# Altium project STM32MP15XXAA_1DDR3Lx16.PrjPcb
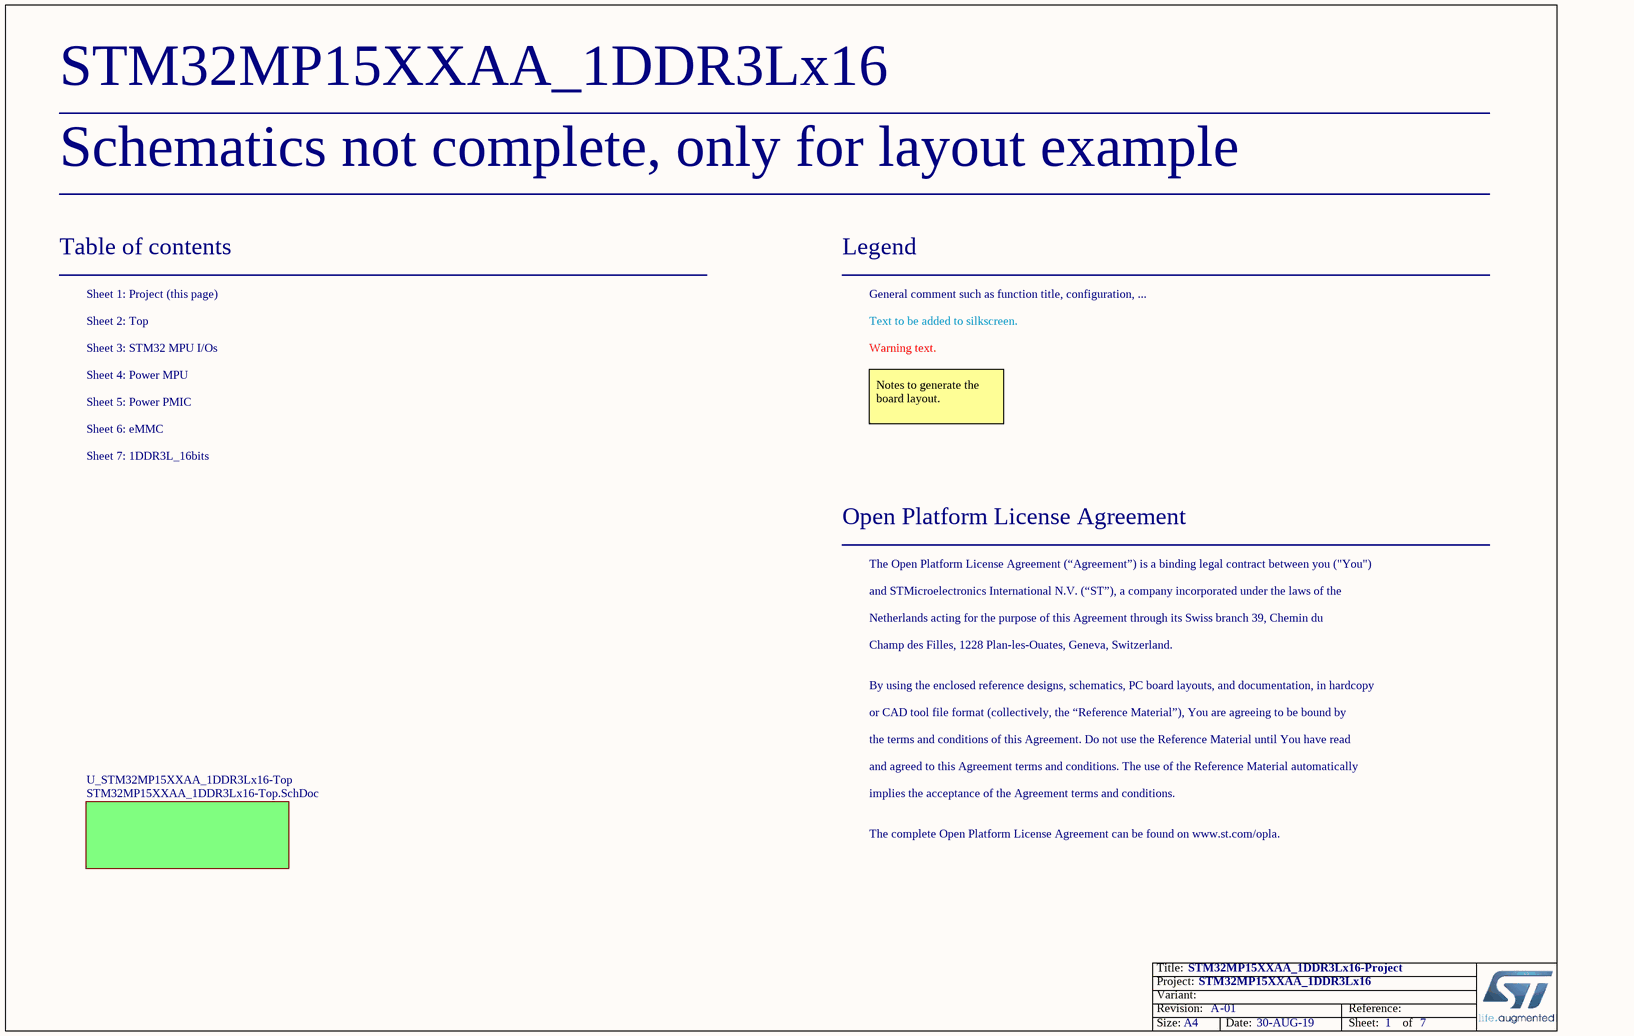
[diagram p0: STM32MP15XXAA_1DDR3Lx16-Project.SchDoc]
Board_Assembly_Revision: 01; Board_Document_Date: 30-AUG-19; Board_Name: STM32MP15XXAA_1DDR3Lx16; Board_PCB_Revision: A
7 sheets, 100 parts. Net scope: flat (ports and power ports of the same name join across sheets).
Board file: STM32MP15XXAA_1DDR3Lx16_A01.PcbDoc
Sheets:
  STM32MP15XXAA_1DDR3Lx16-Project.SchDoc
    U_STM32MP15XXAA_1DDR3Lx16-Top = STM32MP15XXAA_1DDR3Lx16-Top.SchDoc
      U_Power_PMIC = Power_PMIC.SchDoc
      U_Power_MPU = Power_MPU.SchDoc
      U_eMMC = eMMC.SchDoc
      U_STM32_MPU_IOs = STM32_MPU_IOs.SchDoc
      U_1DDR3L_16bits = 1DDR3L_16bits.SchDoc

## Sheet STM32MP15XXAA_1DDR3Lx16-Project.SchDoc: STM32MP15XXAA_1DDR3Lx16-Project
size A4; ApprovedBy: Not used; CheckedBy: Not used; Author: Not used; CompanyName: STMicroelectronics; DrawnBy: Not used; Engineer: Not used; Organization: Not used; Address1: Not used; Address2: Not used; Address3: Not used; Address4: Not used; DocumentNumber: Not used; Revision: Not used; SheetNumber: 1; SheetTotal: 7

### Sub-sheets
U_STM32MP15XXAA_1DDR3Lx16-Top = STM32MP15XXAA_1DDR3Lx16-Top.SchDoc: no entries

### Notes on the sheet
- Schematics not complete, only for layout example
- Table of contents
- Sheet 1: Project (this page)
- Legend
- General comment such as function title, configuration, ...
- Sheet 2: Top
- Sheet 3: STM32 MPU I/Os
- Sheet 4: Power MPU
- Text to be added to silkscreen.
- Warning text.
- Sheet 5: Power PMIC
- Sheet 6: eMMC
- Notes to generate the board layout.
- Sheet 7: 1DDR3L_16bits
- Open Platform License Agreement
- The Open Platform License Agreement (“Agreement”) is a binding legal contract between you ("You")
- and STMicroelectronics International N.V. (“ST”), a company incorporated under the laws of the
- Netherlands acting for the purpose of this Agreement through its Swiss branch 39, Chemin du
- Champ des Filles, 1228 Plan-les-Ouates, Geneva, Switzerland.
- By using the enclosed reference designs, schematics, PC board layouts, and documentation, in hardcopy
- or CAD tool file format (collectively, the “Reference Material”), You are agreeing to be bound by
- the terms and conditions of this Agreement. Do not use the Reference Material until You have read
- and agreed to this Agreement terms and conditions. The use of the Reference Material automatically
- implies the acceptance of the Agreement terms and conditions.
- The complete Open Platform License Agreement can be found on www.st.com/opla.

## Sheet STM32MP15XXAA_1DDR3Lx16-Top.SchDoc: STM32MP15XXAA_1DDR3Lx16-TOP
size A4; Date: Not used; ApprovedBy: Not used; CheckedBy: Not used; Author: Not used; CompanyName: STMicroelectronics; DrawnBy: Not used; Engineer: Not used; Organization: Not used; Address1: Not used; Address2: Not used; Address3: Not used; Address4: Not used; DocumentNumber: Not used; Revision: Not used; SheetNumber: 2; SheetTotal: 7
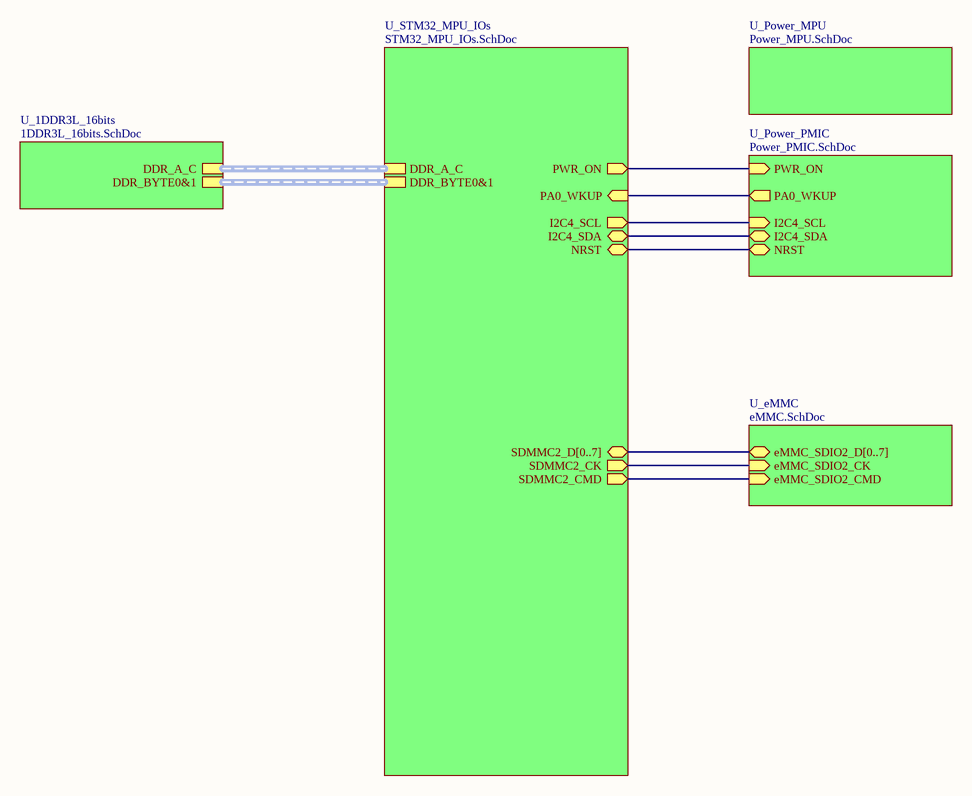
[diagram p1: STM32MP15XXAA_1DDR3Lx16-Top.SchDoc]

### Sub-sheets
U_1DDR3L_16bits = 1DDR3L_16bits.SchDoc: DDR_BYTE0&1 (harness DDR_BYTE_0&1), DDR_A_C (harness DDR_A_C)
U_eMMC = eMMC.SchDoc: eMMC_SDIO2_CK (in), eMMC_SDIO2_D[0..7] (bidir), eMMC_SDIO2_CMD (in)
U_Power_MPU = Power_MPU.SchDoc: no entries
U_Power_PMIC = Power_PMIC.SchDoc: I2C4_SDA (bidir), I2C4_SCL (in), PA0_WKUP (out), NRST (bidir), PWR_ON (in)
U_STM32_MPU_IOs = STM32_MPU_IOs.SchDoc: PA0_WKUP (in), NRST (bidir), PWR_ON (out), I2C4_SCL (out), I2C4_SDA (bidir), DDR_BYTE0&1 (harness DDR_BYTE_0&1), DDR_A_C (harness DDR_A_C), SDMMC2_D[0..7] (bidir), SDMMC2_CMD (out), SDMMC2_CK (out)

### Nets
(unnamed): sheet U_Power_PMIC/I2C4_SDA, sheet U_STM32_MPU_IOs/I2C4_SDA
(unnamed): sheet U_Power_PMIC/I2C4_SCL, sheet U_STM32_MPU_IOs/I2C4_SCL  [a separate net that carries the same name]
(unnamed): sheet U_Power_PMIC/PA0_WKUP, sheet U_STM32_MPU_IOs/PA0_WKUP  [a separate net that carries the same name]
(unnamed): sheet U_Power_PMIC/NRST, sheet U_STM32_MPU_IOs/NRST  [a separate net that carries the same name]
(unnamed): sheet U_Power_PMIC/PWR_ON, sheet U_STM32_MPU_IOs/PWR_ON  [a separate net that carries the same name]
(unnamed): sheet U_eMMC/eMMC_SDIO2_CK, sheet U_STM32_MPU_IOs/SDMMC2_CK  [a separate net that carries the same name]
(unnamed): sheet U_eMMC/eMMC_SDIO2_CMD, sheet U_STM32_MPU_IOs/SDMMC2_CMD  [a separate net that carries the same name]

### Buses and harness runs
bus sheet U_eMMC/eMMC_SDIO2_D[0..7] = sheet U_STM32_MPU_IOs/SDMMC2_D[0..7]
harness sheet U_1DDR3L_16bits/DDR_A_C = sheet U_STM32_MPU_IOs/DDR_A_C
harness sheet U_1DDR3L_16bits/DDR_BYTE0&1 = sheet U_STM32_MPU_IOs/DDR_BYTE0&1

## Sheet Power_PMIC.SchDoc: Power_PMIC
size A3; CompanyName: STMicroelectronics; Organization: Microcontrollers Division; Address1: 12, Rue Jules HOROWITZ; Address2: 38019 Grenoble; Address3: FRANCE; SheetNumber: 5; SheetTotal: 7
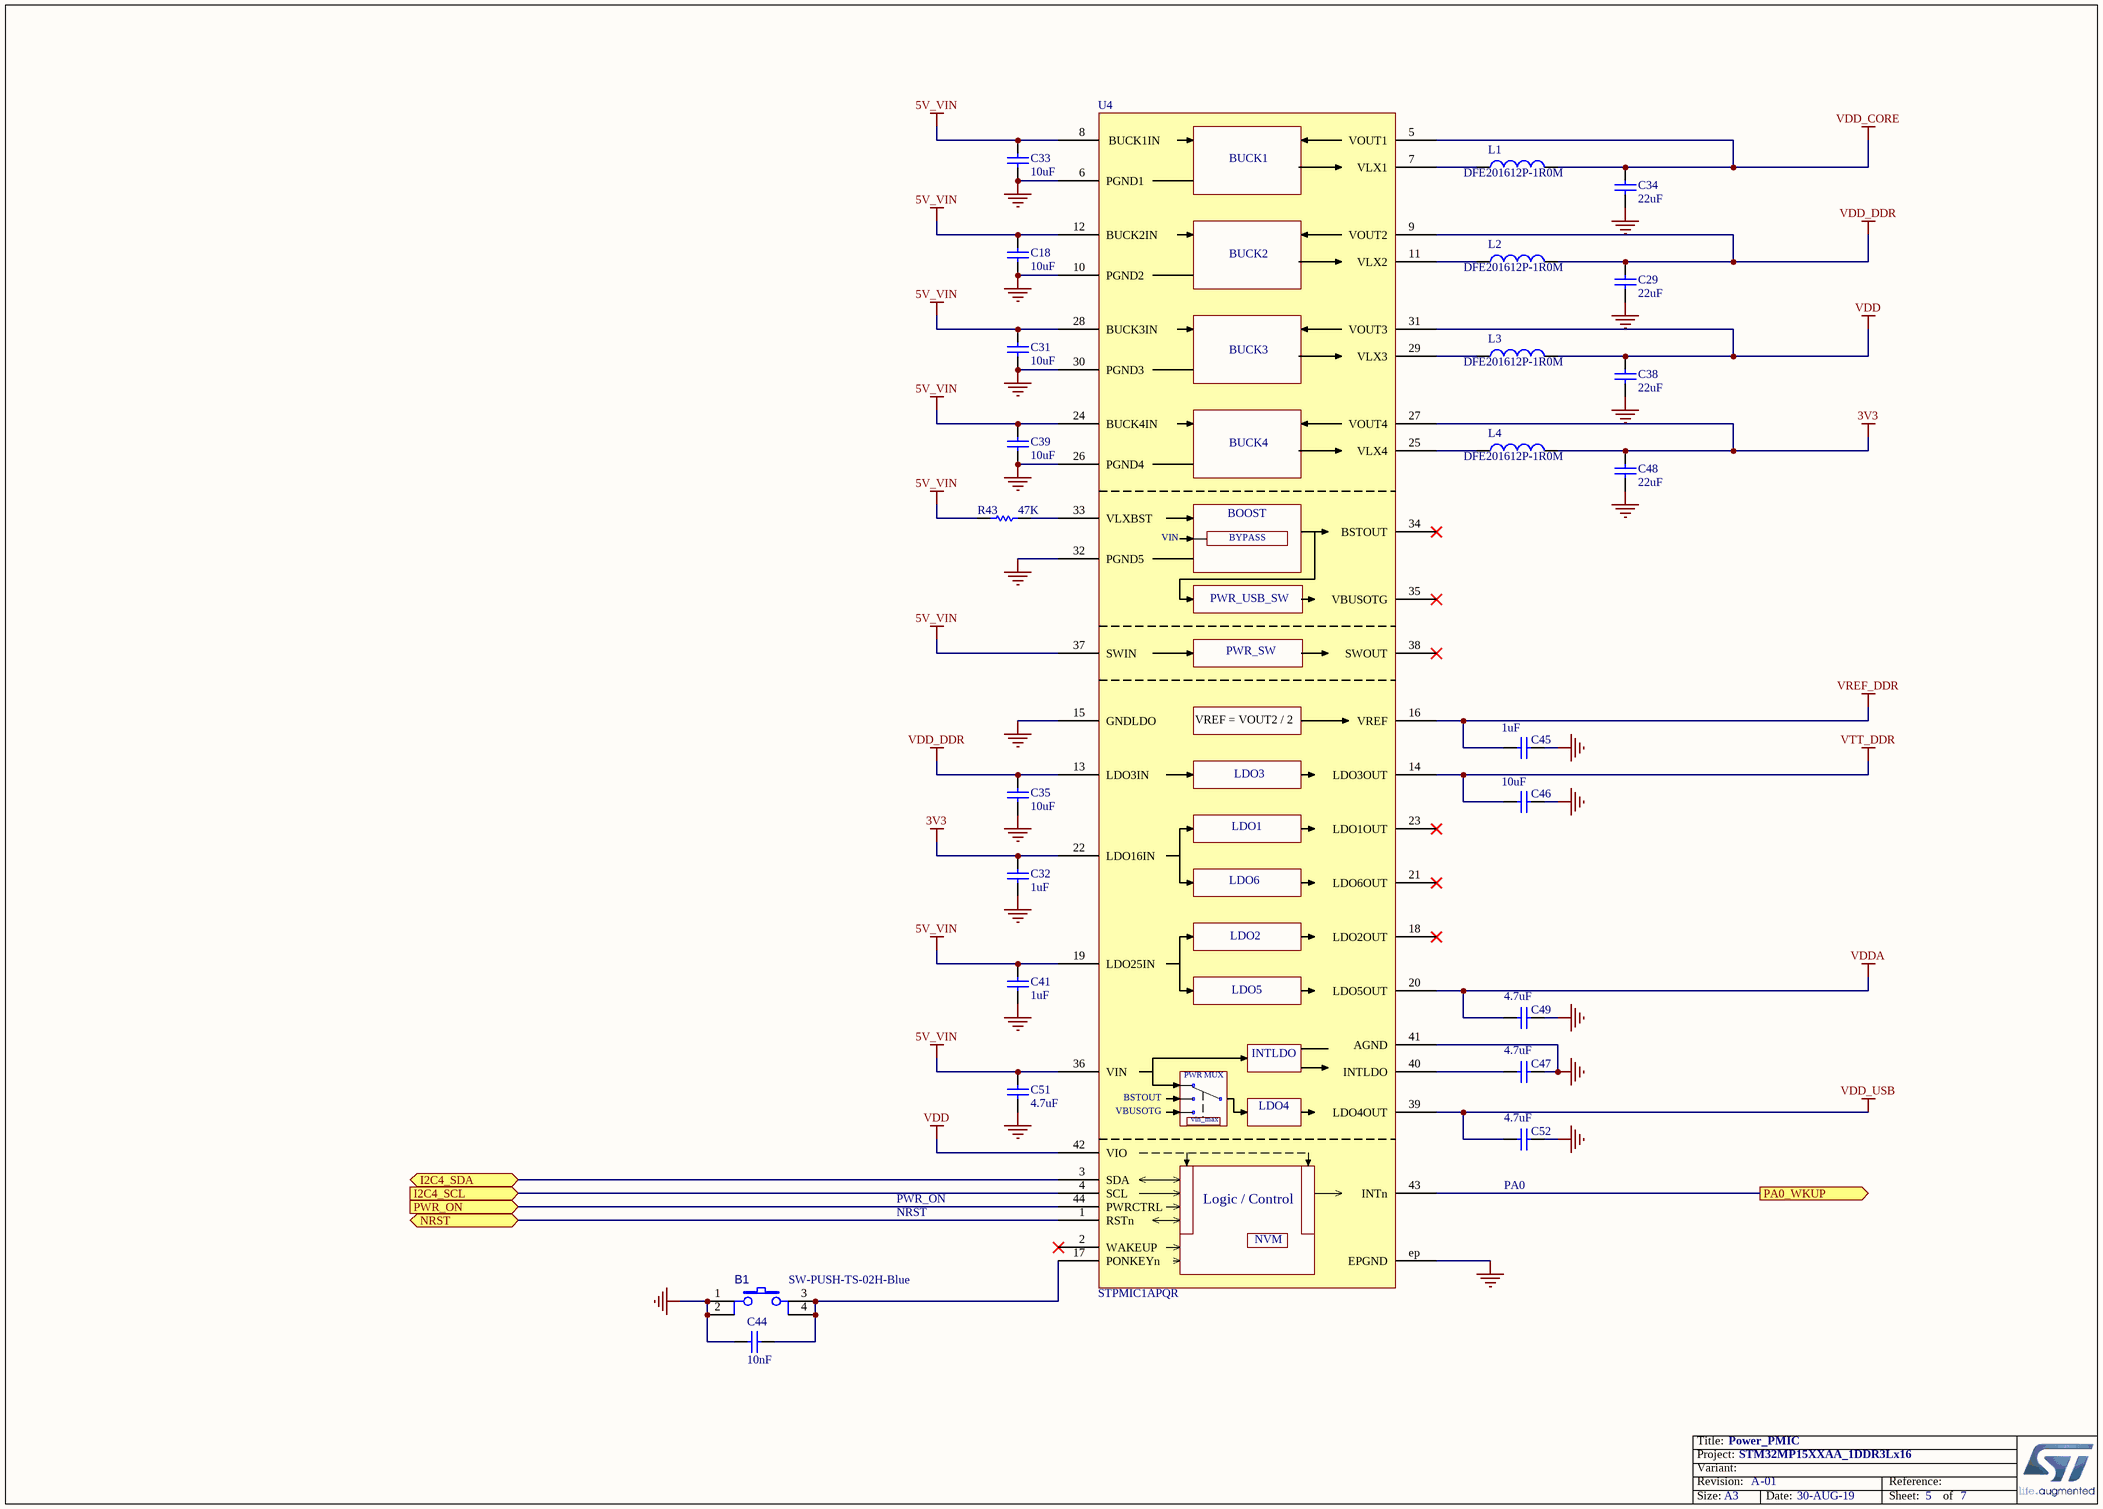
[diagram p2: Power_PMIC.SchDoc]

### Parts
B1  SW-PUSH-TS-02H-Blue  [SWI_JIUBABA_C-TS-02H-2-5-B-V-T_R_BLUE]
C18  value 10uF  [C0603]  (hidden comment: Capacitor)
C29  value 22uF  [C0603]  (hidden comment: Capacitor)
C31  value 10uF  [C0603]  (hidden comment: Capacitor)
C32  value 1uF  [C0402]  (hidden comment: Capacitor)
C33  value 10uF  [C0603]  (hidden comment: Capacitor)
C34  value 22uF  [C0603]  (hidden comment: Capacitor)
C35  value 10uF  [C0603]  (hidden comment: Capacitor)
C38  value 22uF  [C0603]  (hidden comment: Capacitor)
C39  value 10uF  [C0603]  (hidden comment: Capacitor)
C41  value 1uF  [C0402]  (hidden comment: Capacitor)
C44  value 10nF  [C0402]  (hidden comment: Capacitor)
C45  value 1uF  [C0402]  (hidden comment: Capacitor)
C46  value 10uF  [C0603]  (hidden comment: Capacitor)
C47  value 4.7uF  [C0402]  (hidden comment: Capacitor)
C48  value 22uF  [C0603]  (hidden comment: Capacitor)
C49  value 4.7uF  [C0402]  (hidden comment: Capacitor)
C51  value 4.7uF  [C0402]  (hidden comment: Capacitor)
C52  value 4.7uF  [C0402]  (hidden comment: Capacitor)
L1  value DFE201612P-1R0M  [IND_MURATA_DFE201612P]  (hidden comment: Inductor)
L2  value DFE201612P-1R0M  [IND_MURATA_DFE201612P]  (hidden comment: Inductor)
L3  value DFE201612P-1R0M  [IND_MURATA_DFE201612P]  (hidden comment: Inductor)
L4  value DFE201612P-1R0M  [IND_MURATA_DFE201612P]  (hidden comment: Inductor)
R43  value 47K  [R0402]  (hidden comment: Resistor)
U4  value STPMIC1APQR  [ICC_WFQFN44-EPAD_5X6_P040]  (hidden comment: STPMU1)

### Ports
I2C4_SCL (in), I2C4_SDA (bidir), NRST (bidir), PA0_WKUP (out), PWR_ON (in)

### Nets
3V3: C32.2 C48.2 L4.2 U4.22(LDO16IN) U4.27(VOUT4)
5V_VIN: C18.2 C31.2 C33.2 C39.2 C41.2 C51.1 R43.2 U4.8(BUCK1IN) U4.12(BUCK2IN) U4.19(LDO25IN) U4.24(BUCK4IN) U4.28(BUCK3IN) U4.36(VIN) U4.37(SWIN)
GND: B1.1 B1.2 C18.1 C29.1 C31.1 C32.1 C33.1 C34.1 C35.1 C38.1 C39.1 C41.1 C44.1 C45.1 C46.1 C47.1 C48.1 C49.1 C51.2 C52.1 U4.6(PGND1) U4.10(PGND2) U4.15(GNDLDO) U4.26(PGND4) U4.30(PGND3) U4.32(PGND5) U4.41(AGND) U4.ep(EPGND)
VDD: C38.2 L3.2 U4.31(VOUT3) U4.42(VIO)
VDD_CORE: C34.2 L1.2 U4.5(VOUT1)
VDD_DDR: C29.2 C35.2 L2.2 U4.9(VOUT2) U4.13(LDO3IN)
VDD_USB: C52.2 U4.39(LDO4OUT)
VDDA: C49.2 U4.20(LDO5OUT)
VREF_DDR: C45.2 U4.16(VREF)
VTT_DDR: C46.2 U4.14(LDO3OUT)
I2C4_SCL: U4.4(SCL) ; port I2C4_SCL
I2C4_SDA: U4.3(SDA) ; port I2C4_SDA
NRST: U4.1(RSTn) ; port NRST
PA0_WKUP: U4.43(INTn) ; port PA0_WKUP
PWR_ON: U4.44(PWRCTRL) ; port PWR_ON
NetB1_3: B1.3 B1.4 C44.2 U4.17(PONKEYn)
NetC47_2: C47.2 U4.40(INTLDO)
NetL1_1: L1.1 U4.7(VLX1)
NetL2_1: L2.1 U4.11(VLX2)
NetL3_1: L3.1 U4.29(VLX3)
NetL4_1: L4.1 U4.25(VLX4)
NetR43_1: R43.1 U4.33(VLXBST)

Not connected (* = marked no-connect by the designer): U4 2(WAKEUP)* 18(LDO2OUT)* 21(LDO6OUT)* 23(LDO1OUT)* 34(BSTOUT)* 35(VBUSOTG)* 38(SWOUT)*

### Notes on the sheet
- (near C52) PA0
- NRST
- PWR_ON

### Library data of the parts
B1 = MCD-00172: Switch HW SMD blue; Part_Type: Misc; Manufacturer_Part_Number: C-TS-02H-2.5-B-V-T/R BLUE; Manufacturer: JIUBABA; Provided_By: SUBCO
C18 C31 C33 C35 C39 C46 = MCD-00099: Capacitor, MLCC, 10uF, 10V, X5R, 10%, 0603, T=0,8mm; Manufacturer_Part_Number: GRM188R61A106KE69D; Manufacturer: MURATA; Provided_By: SUBCO; ECCN_US: EAR99; ECCN_EU: NEC
C29 C34 C38 C48 = MCD-00100: Capacitor, MLCC, 22uF, 6V3, X5R, 20%, 0603, T=0,8mm; Manufacturer_Part_Number: GRM188R60J226MEA0J; Manufacturer: MURATA; Provided_By: SUBCO; ECCN_US: EAR99; ECCN_EU: NEC
C32 C41 C45 = MCD-00095: Capacitor, MLCC, 1uF, 25V, X5R, 10%, 0402, T=0,5mm; Manufacturer_Part_Number: GRM155R61E105KA12; Manufacturer: MURATA; Alternate_Manufacturer_Part_Number: GRM155R60J105KE19; Provided_By: SUBCO; ECCN_US: EAR99; ECCN_EU: NEC
C44 = MCD-00011: Capacitor, MLCC, 10nF, 16V, X7R, 10%, 0402, T=0.5mm; Manufacturer_Part_Number: CC0402KRX7R7BB103; Manufacturer: YAGEO; Provided_By: SUBCO; ECCN_US: EAR99; ECCN_EU: NEC
C47 C49 C51 C52 = MCD-01356: Capacitor, MLCC, 4.7uF, 6V3, X5R, 20%, 0402, T=0,5mm; Manufacturer_Part_Number: GRM155R60J475ME47; Manufacturer: MURATA; Alternate_Manufacturer_Part_Number: GRM155R60J475ME87; Provided_By: SUBCO; ECCN_US: EAR99; ECCN_EU: NEC
L1-L4 = MCD-01491: Inductors 1.0uH 54mOhms3.3A +/-20% 2016; Manufacturer: MURATA; Provided_By: SUBCO
R43 = MCD-00063: Resistor,47K,0402,1%,1/16W; Manufacturer_Part_Number: RC0402FR-0747KL; Manufacturer: YAGEO; Provided_By: SUBCO; ECCN_US: EAR99; ECCN_EU: NEC
U4 = MCD-01650: ST PMIC:  4 step-down + 1 advanced boost SMPS, 6 LDOs, 2 pwr switches, DDR Vref, NVM option 'A' for IO@3.3V; Part_Type: IC; Manufacturer: STMICROELECTRONICS; BMS_Part_Number: 9177723; ECCN_US: EAR99; ECCN_EU: NEC; Provided_By: SUBCO with ST control

## Sheet Power_MPU.SchDoc: Power_MPU
size A3; CompanyName: STMicroelectronics; SheetNumber: 4; SheetTotal: 7
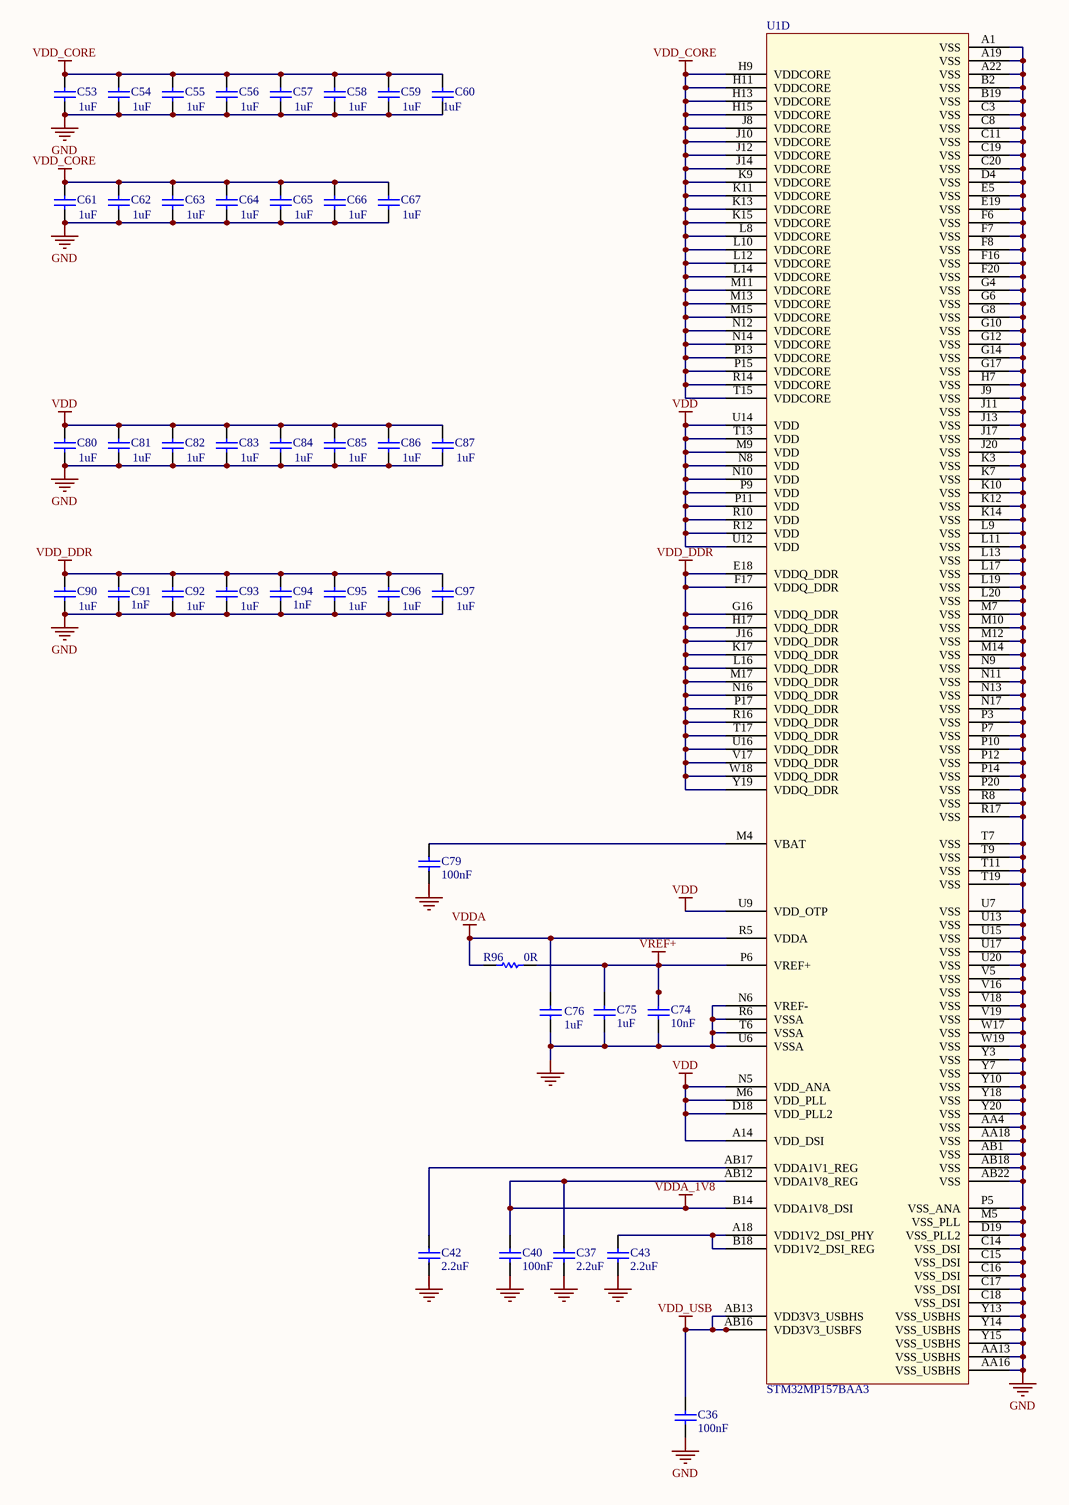
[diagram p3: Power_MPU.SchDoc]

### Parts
C36  value 100nF  [C0402]  (hidden comment: Capacitor)
C37  value 2.2uF  [C0402]  (hidden comment: Capacitor)
C40  value 100nF  [C0402]  (hidden comment: Capacitor)
C42  value 2.2uF  [C0402]  (hidden comment: Capacitor)
C43  value 2.2uF  [C0402]  (hidden comment: Capacitor)
C53  value 1uF  [C0402]  (hidden comment: Capacitor)
C54  value 1uF  [C0402]  (hidden comment: Capacitor)
C55  value 1uF  [C0402]  (hidden comment: Capacitor)
C56  value 1uF  [C0402]  (hidden comment: Capacitor)
C57  value 1uF  [C0402]  (hidden comment: Capacitor)
C58  value 1uF  [C0402]  (hidden comment: Capacitor)
C59  value 1uF  [C0402]  (hidden comment: Capacitor)
C60  value 1uF  [C0402]  (hidden comment: Capacitor)
C61  value 1uF  [C0402]  (hidden comment: Capacitor)
C62  value 1uF  [C0402]  (hidden comment: Capacitor)
C63  value 1uF  [C0402]  (hidden comment: Capacitor)
C64  value 1uF  [C0402]  (hidden comment: Capacitor)
C65  value 1uF  [C0402]  (hidden comment: Capacitor)
C66  value 1uF  [C0402]  (hidden comment: Capacitor)
C67  value 1uF  [C0402]  (hidden comment: Capacitor)
C74  value 10nF  [C0402]  (hidden comment: Capacitor)
C75  value 1uF  [C0402]  (hidden comment: Capacitor)
C76  value 1uF  [C0402]  (hidden comment: Capacitor)
C79  value 100nF  [C0402]  (hidden comment: Capacitor)
C80  value 1uF  [C0402]  (hidden comment: Capacitor)
C81  value 1uF  [C0402]  (hidden comment: Capacitor)
C82  value 1uF  [C0402]  (hidden comment: Capacitor)
C83  value 1uF  [C0402]  (hidden comment: Capacitor)
C84  value 1uF  [C0402]  (hidden comment: Capacitor)
C85  value 1uF  [C0402]  (hidden comment: Capacitor)
C86  value 1uF  [C0402]  (hidden comment: Capacitor)
C87  value 1uF  [C0402]  (hidden comment: Capacitor)
C90  value 1uF  [C0402]  (hidden comment: Capacitor)
C91  value 1nF  [C0402]  (hidden comment: Capacitor)
C92  value 1uF  [C0402]  (hidden comment: Capacitor)
C93  value 1uF  [C0402]  (hidden comment: Capacitor)
C94  value 1nF  [C0402]  (hidden comment: Capacitor)
C95  value 1uF  [C0402]  (hidden comment: Capacitor)
C96  value 1uF  [C0402]  (hidden comment: Capacitor)
C97  value 1uF  [C0402]  (hidden comment: Capacitor)
R96  value 0R  [R0402]  (hidden comment: Resistor)
U1  STM32MP157BAA3  [ICC_LFBGA448_18X18_STM32MP157BAA3_P080]  (part D of 5)

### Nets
GND: C36.1 C37.1 C40.1 C42.1 C43.1 C53.1 C54.1 C55.1 C56.1 C57.1 C58.1 C59.1 C60.1 C61.1 C62.1 C63.1 C64.1 C65.1 C66.1 C67.1 C74.1 C75.1 C76.1 C79.1 C80.1 C81.1 C82.1 C83.1 C84.1 C85.1 C86.1 C87.1 C90.1 C91.1 C92.1 C93.1 C94.1 C95.1 C96.1 C97.1 U1.A1(VSS) U1.A19(VSS) U1.A22(VSS) U1.AA4(VSS) U1.AA13(VSS_USBHS) U1.AA16(VSS_USBHS) U1.AA18(VSS) U1.AB1(VSS) U1.AB18(VSS) U1.AB22(VSS) U1.B2(VSS) U1.B19(VSS) U1.C3(VSS) U1.C8(VSS) U1.C11(VSS) U1.C14(VSS_DSI) U1.C15(VSS_DSI) U1.C16(VSS_DSI) U1.C17(VSS_DSI) U1.C18(VSS_DSI) U1.C19(VSS) U1.C20(VSS) U1.D4(VSS) U1.D19(VSS_PLL2) U1.E5(VSS) U1.E19(VSS) U1.F6(VSS) U1.F7(VSS) U1.F8(VSS) U1.F16(VSS) U1.F20(VSS) U1.G4(VSS) U1.G6(VSS) U1.G8(VSS) U1.G10(VSS) U1.G12(VSS) U1.G14(VSS) U1.G17(VSS) U1.H7(VSS) U1.J9(VSS) U1.J11(VSS) U1.J13(VSS) U1.J17(VSS) U1.J20(VSS) U1.K3(VSS) U1.K7(VSS) U1.K10(VSS) U1.K12(VSS) U1.K14(VSS) U1.L9(VSS) U1.L11(VSS) U1.L13(VSS) U1.L17(VSS) U1.L19(VSS) U1.L20(VSS) U1.M5(VSS_PLL) U1.M7(VSS) U1.M10(VSS) U1.M12(VSS) U1.M14(VSS) U1.N6(VREF-) U1.N9(VSS) U1.N11(VSS) U1.N13(VSS) U1.N17(VSS) U1.P3(VSS) U1.P5(VSS_ANA) U1.P7(VSS) U1.P10(VSS) U1.P12(VSS) U1.P14(VSS) U1.P20(VSS) U1.R6(VSSA) U1.R8(VSS) U1.R17(VSS) U1.T6(VSSA) U1.T7(VSS) U1.T9(VSS) U1.T11(VSS) U1.T19(VSS) U1.U6(VSSA) U1.U7(VSS) U1.U13(VSS) U1.U15(VSS) U1.U17(VSS) U1.U20(VSS) U1.V5(VSS) U1.V16(VSS) U1.V18(VSS) U1.V19(VSS) U1.W17(VSS) U1.W19(VSS) U1.Y3(VSS) U1.Y7(VSS) U1.Y10(VSS) U1.Y13(VSS_USBHS) U1.Y14(VSS_USBHS) U1.Y15(VSS_USBHS) U1.Y18(VSS) U1.Y20(VSS)
VDD: C80.2 C81.2 C82.2 C83.2 C84.2 C85.2 C86.2 C87.2 U1.A14(VDD_DSI) U1.D18(VDD_PLL2) U1.M6(VDD_PLL) U1.M9(VDD) U1.N5(VDD_ANA) U1.N8(VDD) U1.N10(VDD) U1.P9(VDD) U1.P11(VDD) U1.R10(VDD) U1.R12(VDD) U1.T13(VDD) U1.U9(VDD_OTP) U1.U12(VDD) U1.U14(VDD)
VDD_CORE: C53.2 C54.2 C55.2 C56.2 C57.2 C58.2 C59.2 C60.2 C61.2 C62.2 C63.2 C64.2 C65.2 C66.2 C67.2 U1.H9(VDDCORE) U1.H11(VDDCORE) U1.H13(VDDCORE) U1.H15(VDDCORE) U1.J8(VDDCORE) U1.J10(VDDCORE) U1.J12(VDDCORE) U1.J14(VDDCORE) U1.K9(VDDCORE) U1.K11(VDDCORE) U1.K13(VDDCORE) U1.K15(VDDCORE) U1.L8(VDDCORE) U1.L10(VDDCORE) U1.L12(VDDCORE) U1.L14(VDDCORE) U1.M11(VDDCORE) U1.M13(VDDCORE) U1.M15(VDDCORE) U1.N12(VDDCORE) U1.N14(VDDCORE) U1.P13(VDDCORE) U1.P15(VDDCORE) U1.R14(VDDCORE) U1.T15(VDDCORE)
VDD_DDR: C90.2 C91.2 C92.2 C93.2 C94.2 C95.2 C96.2 C97.2 U1.E18(VDDQ_DDR) U1.F17(VDDQ_DDR) U1.G16(VDDQ_DDR) U1.H17(VDDQ_DDR) U1.J16(VDDQ_DDR) U1.K17(VDDQ_DDR) U1.L16(VDDQ_DDR) U1.M17(VDDQ_DDR) U1.N16(VDDQ_DDR) U1.P17(VDDQ_DDR) U1.R16(VDDQ_DDR) U1.T17(VDDQ_DDR) U1.U16(VDDQ_DDR) U1.V17(VDDQ_DDR) U1.W18(VDDQ_DDR) U1.Y19(VDDQ_DDR)
VDD_USB: C36.2 U1.AB13(VDD3V3_USBHS) U1.AB16(VDD3V3_USBFS)
VDDA: C76.2 R96.1 U1.R5(VDDA)
VDDA_1V8: C37.2 C40.2 U1.AB12(VDDA1V8_REG) U1.B14(VDDA1V8_DSI)
VREF+: C74.2 C75.2 R96.2 U1.P6(VREF+)
NetC42_2: C42.2 U1.AB17(VDDA1V1_REG)
NetC43_2: C43.2 U1.A18(VDD1V2_DSI_PHY) U1.B18(VDD1V2_DSI_REG)
NetC79_2: C79.2 U1.M4(VBAT)

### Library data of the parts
C36 C40 C79 = MCD-00006: Capacitor, MLCC, 100nF, 16V, X7R, 10%, 0402, T=0.5mm; Manufacturer_Part_Number: CC0402KRX7R7BB104; Manufacturer: YAGEO; Alternate_Manufacturer_Part_Number: GCM155R71C104KA55D; Alternate_Manufacturer: MURATA; Provided_By: SUBCO; ECCN_US: EAR99; ECCN_EU: NEC
C37 C42 C43 = MCD-01823: Capacitor,MLCC,2.2uF,6V3,X5R,10%,0402,T=0.5; Manufacturer_Part_Number: GRM155R60J225KE95D; Manufacturer: MURATA; ECCN_US: EAR99; ECCN_EU: NEC; Provided_By: SUBCO
C53-C67 C75 C76 C80-C87 C90 C92 C93 C95-C97 = MCD-00095: as C32 on sheet Power_PMIC
C74 = MCD-00011: Capacitor, MLCC, 10nF, 16V, X7R, 10%, 0402, T=0.5mm; Manufacturer_Part_Number: CC0402KRX7R7BB103; Manufacturer: YAGEO; ECCN_US: EAR99; ECCN_EU: NEC; Provided_By: SUBCO
C91 C94 = MCD-00198: Capacitor, MLCC, 1nF, 16V, X7R, 10%, 0402, T=0.5mm; Manufacturer_Part_Number: CC0402KRX7R7BB102; Manufacturer: YAGEO; Provided_By: SUBCO; ECCN_US: EAR99; ECCN_EU: NEC
R96 = MCD-00052: Resistor,0R,0402,5%,1/16W; Manufacturer_Part_Number: RC0402JR-070RL; Manufacturer: YAGEO; Provided_By: SUBCO; ECCN_US: EAR99; ECCN_EU: NEC
U1 = MCD-00618: MPU LFBGA18x18 with crypto; Part_Type: IC; Manufacturer: STMICROELECTRONICS; ECCN_US: 3A991A2; ECCN_EU: NEC; Provided_By: SUBCO with ST control

## Sheet eMMC.SchDoc: eMMC
size A3; CompanyName: STMicroelectronics; Address1: 12, Rue Jules HOROWITZ; Address2: 38019 Grenoble; Address3: FRANCE; SheetNumber: 6; SheetTotal: 7
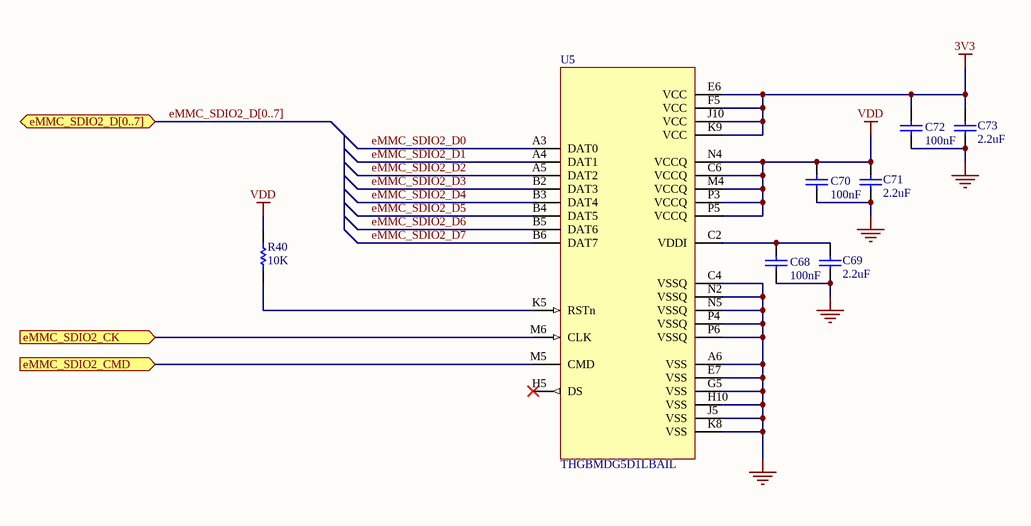
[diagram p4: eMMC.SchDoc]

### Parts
C68  value 100nF  [C0402]  (hidden comment: Capacitor)
C69  value 2.2uF  [C0603]  (hidden comment: Capacitor)
C70  value 100nF  [C0402]  (hidden comment: Capacitor)
C71  value 2.2uF  [C0603]  (hidden comment: Capacitor)
C72  value 100nF  [C0402]  (hidden comment: Capacitor)
C73  value 2.2uF  [C0603]  (hidden comment: Capacitor)
R40  value 10K  [R0402]  (hidden comment: Resistor)
U5  value THGBMDG5D1LBAIL  [ICC_P-WFBGA153_13X11P5_P050]  (hidden comment: eMMC_THGBMDG5D1LBAIL)

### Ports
eMMC_SDIO2_CK (in), eMMC_SDIO2_CMD (in), eMMC_SDIO2_D[0..7] (bidir)

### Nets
3V3: C72.2 C73.2 U5.E6(VCC) U5.F5(VCC) U5.J10(VCC) U5.K9(VCC)
GND: C68.1 C69.1 C70.1 C71.1 C72.1 C73.1 U5.A6(VSS) U5.C4(VSSQ) U5.E7(VSS) U5.G5(VSS) U5.H10(VSS) U5.J5(VSS) U5.K8(VSS) U5.N2(VSSQ) U5.N5(VSSQ) U5.P4(VSSQ) U5.P6(VSSQ)
VDD: C70.2 C71.2 R40.2 U5.C6(VCCQ) U5.M4(VCCQ) U5.N4(VCCQ) U5.P3(VCCQ) U5.P5(VCCQ)
eMMC_SDIO2_CK: U5.M6(CLK) ; port eMMC_SDIO2_CK
eMMC_SDIO2_CMD: U5.M5(CMD) ; port eMMC_SDIO2_CMD
eMMC_SDIO2_D0: U5.A3(DAT0)
eMMC_SDIO2_D1: U5.A4(DAT1)
eMMC_SDIO2_D2: U5.A5(DAT2)
eMMC_SDIO2_D3: U5.B2(DAT3)
eMMC_SDIO2_D4: U5.B3(DAT4)
eMMC_SDIO2_D5: U5.B4(DAT5)
eMMC_SDIO2_D6: U5.B5(DAT6)
eMMC_SDIO2_D7: U5.B6(DAT7)
NetC68_2: C68.2 C69.2 U5.C2(VDDI)
NetR40_1: R40.1 U5.K5(RSTn)

Not connected (* = marked no-connect by the designer): U5 H5(DS)*

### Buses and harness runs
bus eMMC_SDIO2_D[0..7] = port eMMC_SDIO2_D[0..7]

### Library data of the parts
C68 C70 C72 = MCD-00006: as C36 on sheet Power_MPU
C69 C71 C73 = MCD-00012: Capacitor, MLCC, 2.2uF, 10V, X5R, 10%, 0603, T=0,8mm; Manufacturer_Part_Number: CC0603KRX5R6BB225; Manufacturer: YAGEO; Alternate_Manufacturer_Part_Number: C0603C225K8PACTU; Alternate_Manufacturer: KEMET; BMS_Part_Number: 9142010; Provided_By: SUBCO; ECCN_US: EAR99; ECCN_EU: NEC
R40 = MCD-00053: Resistor,10K,0402,1%,1/16W; Manufacturer_Part_Number: RC0402FR-0710KL; Manufacturer: YAGEO; BMS_Part_Number: 9131590; Provided_By: SUBCO; ECCN_US: EAR99; ECCN_EU: NEC
U5 = MCD-00110: Memory,e-MMC,4GB,3V3,WFBGA,153pins; Part_Type: IC; Manufacturer: TOSHIBA; BMS_Part_Number: 9171005; Provided_By: SUBCO; ECCN_US: 3A991; ECCN_EU: NEC

## Sheet STM32_MPU_IOs.SchDoc: MPU
size A3; SheetNumber: 3; SheetTotal: 7
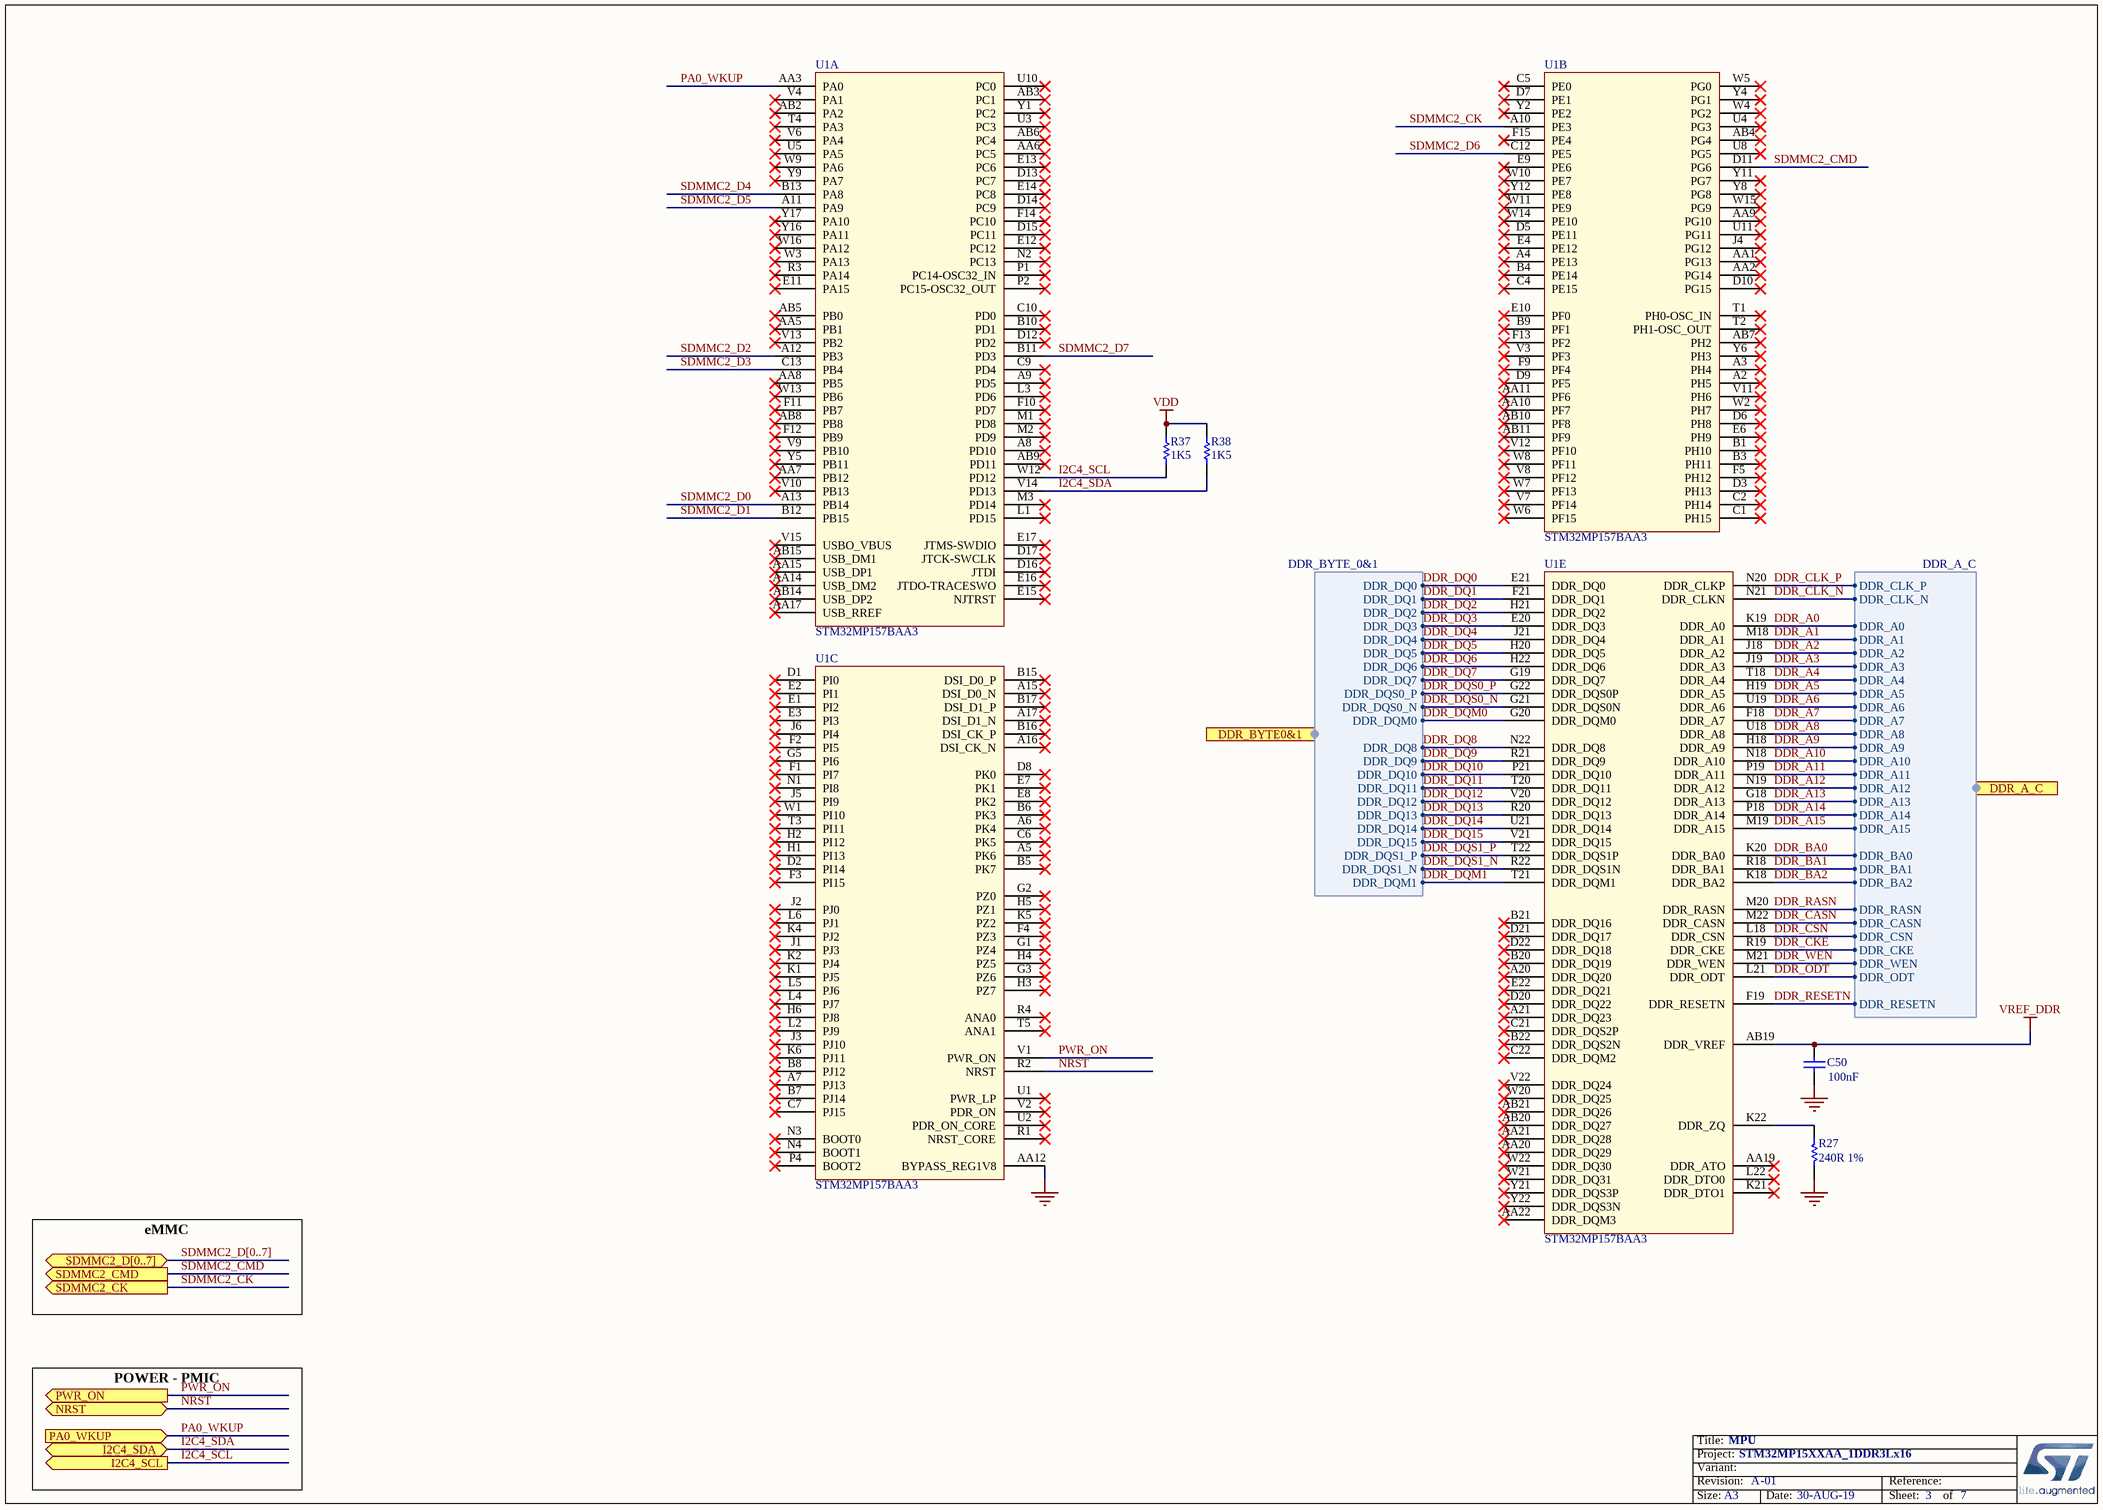
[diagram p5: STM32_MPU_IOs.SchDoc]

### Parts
C50  value 100nF  [C0402]  (hidden comment: Capacitor)
R27  value 240R 1%  [R0402]  (hidden comment: Resistor)
R37  value 1K5  [R0402]  (hidden comment: Resistor)
R38  value 1K5  [R0402]  (hidden comment: Resistor)
U1  STM32MP157BAA3  [ICC_LFBGA448_18X18_STM32MP157BAA3_P080]  (parts A,B,C,E of 5)

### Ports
DDR_A_C (harness DDR_A_C), DDR_BYTE0&1 (harness DDR_BYTE_0&1), I2C4_SCL (out), I2C4_SDA (bidir), NRST (bidir), PA0_WKUP (in), PWR_ON (out), SDMMC2_CK (out), SDMMC2_CMD (out), SDMMC2_D[0..7] (bidir)

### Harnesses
DDR_BYTE_0&1: DDR_DQ0, DDR_DQ1, DDR_DQ2, DDR_DQ3, DDR_DQ4, DDR_DQ5, DDR_DQ6, DDR_DQ7, DDR_DQS0_P, DDR_DQS0_N, DDR_DQM0, DDR_DQ8, DDR_DQ9, DDR_DQ10, DDR_DQ11, DDR_DQ12, DDR_DQ13, DDR_DQ14, DDR_DQ15, DDR_DQS1_P, DDR_DQS1_N, DDR_DQM1
DDR_A_C: DDR_CLK_P, DDR_CLK_N, DDR_A0, DDR_A1, DDR_A2, DDR_A3, DDR_A4, DDR_A5, DDR_A6, DDR_A7, DDR_A8, DDR_A9, DDR_A10, DDR_A11, DDR_A12, DDR_A13, DDR_A14, DDR_BA0, DDR_BA1, DDR_BA2, DDR_RASN, DDR_CASN, DDR_CSN, DDR_CKE, DDR_WEN, DDR_ODT, DDR_RESETN, DDR_A15

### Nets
GND: C50.1 R27.2 U1.AA12(BYPASS_REG1V8)
VDD: R37.1 R38.1
VREF_DDR: C50.2 U1.AB19(DDR_VREF)
DDR_A0: U1.K19(DDR_A0) ; port DDR_A_C.DDR_A0
DDR_A1: U1.M18(DDR_A1) ; port DDR_A_C.DDR_A1
DDR_A2: U1.J18(DDR_A2) ; port DDR_A_C.DDR_A2
DDR_A3: U1.J19(DDR_A3) ; port DDR_A_C.DDR_A3
DDR_A4: U1.T18(DDR_A4) ; port DDR_A_C.DDR_A4
DDR_A5: U1.H19(DDR_A5) ; port DDR_A_C.DDR_A5
DDR_A6: U1.U19(DDR_A6) ; port DDR_A_C.DDR_A6
DDR_A7: U1.F18(DDR_A7) ; port DDR_A_C.DDR_A7
DDR_A8: U1.U18(DDR_A8) ; port DDR_A_C.DDR_A8
DDR_A9: U1.H18(DDR_A9) ; port DDR_A_C.DDR_A9
DDR_A10: U1.N18(DDR_A10) ; port DDR_A_C.DDR_A10
DDR_A11: U1.P19(DDR_A11) ; port DDR_A_C.DDR_A11
DDR_A12: U1.N19(DDR_A12) ; port DDR_A_C.DDR_A12
DDR_A13: U1.G18(DDR_A13) ; port DDR_A_C.DDR_A13
DDR_A14: U1.P18(DDR_A14) ; port DDR_A_C.DDR_A14
DDR_A15: U1.M19(DDR_A15) ; port DDR_A_C.DDR_A15
DDR_BA0: U1.K20(DDR_BA0) ; port DDR_A_C.DDR_BA0
DDR_BA1: U1.R18(DDR_BA1) ; port DDR_A_C.DDR_BA1
DDR_BA2: U1.K18(DDR_BA2) ; port DDR_A_C.DDR_BA2
DDR_CASN: U1.M22(DDR_CASN) ; port DDR_A_C.DDR_CASN
DDR_CKE: U1.R19(DDR_CKE) ; port DDR_A_C.DDR_CKE
DDR_CLK_N: U1.N21(DDR_CLKN) ; port DDR_A_C.DDR_CLK_N
DDR_CLK_P: U1.N20(DDR_CLKP) ; port DDR_A_C.DDR_CLK_P
DDR_CSN: U1.L18(DDR_CSN) ; port DDR_A_C.DDR_CSN
DDR_DQ0: U1.E21(DDR_DQ0) ; port DDR_BYTE0&1.DDR_DQ0
DDR_DQ1: U1.F21(DDR_DQ1) ; port DDR_BYTE0&1.DDR_DQ1
DDR_DQ2: U1.H21(DDR_DQ2) ; port DDR_BYTE0&1.DDR_DQ2
DDR_DQ3: U1.E20(DDR_DQ3) ; port DDR_BYTE0&1.DDR_DQ3
DDR_DQ4: U1.J21(DDR_DQ4) ; port DDR_BYTE0&1.DDR_DQ4
DDR_DQ5: U1.H20(DDR_DQ5) ; port DDR_BYTE0&1.DDR_DQ5
DDR_DQ6: U1.H22(DDR_DQ6) ; port DDR_BYTE0&1.DDR_DQ6
DDR_DQ7: U1.G19(DDR_DQ7) ; port DDR_BYTE0&1.DDR_DQ7
DDR_DQ8: U1.N22(DDR_DQ8) ; port DDR_BYTE0&1.DDR_DQ8
DDR_DQ9: U1.R21(DDR_DQ9) ; port DDR_BYTE0&1.DDR_DQ9
DDR_DQ10: U1.P21(DDR_DQ10) ; port DDR_BYTE0&1.DDR_DQ10
DDR_DQ11: U1.T20(DDR_DQ11) ; port DDR_BYTE0&1.DDR_DQ11
DDR_DQ12: U1.V20(DDR_DQ12) ; port DDR_BYTE0&1.DDR_DQ12
DDR_DQ13: U1.R20(DDR_DQ13) ; port DDR_BYTE0&1.DDR_DQ13
DDR_DQ14: U1.U21(DDR_DQ14) ; port DDR_BYTE0&1.DDR_DQ14
DDR_DQ15: U1.V21(DDR_DQ15) ; port DDR_BYTE0&1.DDR_DQ15
DDR_DQM0: U1.G20(DDR_DQM0) ; port DDR_BYTE0&1.DDR_DQM0
DDR_DQM1: U1.T21(DDR_DQM1) ; port DDR_BYTE0&1.DDR_DQM1
DDR_DQS0_N: U1.G21(DDR_DQS0N) ; port DDR_BYTE0&1.DDR_DQS0_N
DDR_DQS0_P: U1.G22(DDR_DQS0P) ; port DDR_BYTE0&1.DDR_DQS0_P
DDR_DQS1_N: U1.R22(DDR_DQS1N) ; port DDR_BYTE0&1.DDR_DQS1_N
DDR_DQS1_P: U1.T22(DDR_DQS1P) ; port DDR_BYTE0&1.DDR_DQS1_P
DDR_ODT: U1.L21(DDR_ODT) ; port DDR_A_C.DDR_ODT
DDR_RASN: U1.M20(DDR_RASN) ; port DDR_A_C.DDR_RASN
DDR_RESETN: U1.F19(DDR_RESETN) ; port DDR_A_C.DDR_RESETN
DDR_WEN: U1.M21(DDR_WEN) ; port DDR_A_C.DDR_WEN
I2C4_SCL: R37.2 U1.W12(PD12) ; port I2C4_SCL
I2C4_SDA: R38.2 U1.V14(PD13) ; port I2C4_SDA
NRST: U1.R2(NRST) ; port NRST
PA0_WKUP: U1.AA3(PA0) ; port PA0_WKUP
PWR_ON: U1.V1(PWR_ON) ; port PWR_ON
SDMMC2_CK: U1.A10(PE3) ; port SDMMC2_CK
SDMMC2_CMD: U1.D11(PG6) ; port SDMMC2_CMD
SDMMC2_D0: U1.A13(PB14)
SDMMC2_D1: U1.B12(PB15)
SDMMC2_D2: U1.A12(PB3)
SDMMC2_D3: U1.C13(PB4)
SDMMC2_D4: U1.B13(PA8)
SDMMC2_D5: U1.A11(PA9)
SDMMC2_D6: U1.C12(PE5)
SDMMC2_D7: U1.B11(PD3)
NetR27_1: R27.1 U1.K22(DDR_ZQ)

Not connected (* = marked no-connect by the designer): U1 A2(PH5)* A3(PH4)* A4(PE13)* A5(PK6)* A6(PK4)* A7(PJ13)* A8(PD10)* A9(PD5)* A15(DSI_D0_N)* A16(DSI_CK_N)* A17(DSI_D1_N)* A20(DDR_DQ20)* A21(DDR_DQ23)* AA1(PG13)* AA2(PG14)* AA5(PB1)* AA6(PC5)* AA7(PB12)* AA8(PB5)* AA9(PG10)* AA10(PF7)* AA11(PF6)* AA14(USB_DM2)* AA15(USB_DP1)* AA17(USB_RREF)* AA19(DDR_ATO)* AA20(DDR_DQ29)* AA21(DDR_DQ28)* AA22(DDR_DQM3)* AB2(PA2)* AB3(PC1)* AB4(PG4)* AB5(PB0)* AB6(PC4)* AB7(PH2)* AB8(PB8)* AB9(PD11)* AB10(PF8)* AB11(PF9)* AB14(USB_DP2)* AB15(USB_DM1)* AB20(DDR_DQ27)* AB21(DDR_DQ26)* B1(PH10)* B3(PH11)* B4(PE14)* B5(PK7)* B6(PK3)* B7(PJ14)* B8(PJ12)* B9(PF1)* B10(PD1)* B15(DSI_D0_P)* B16(DSI_CK_P)* B17(DSI_D1_P)* B20(DDR_DQ19)* B21(DDR_DQ16)* B22(DDR_DQS2N)* C1(PH15)* C2(PH14)* C4(PE15)* C5(PE0)* C6(PK5)* C7(PJ15)* C9(PD4)* C10(PD0)* C21(DDR_DQS2P)* C22(DDR_DQM2)* D1(PI0)* D2(PI14)* D3(PH13)* D5(PE11)* D6(PH8)* D7(PE1)* D8(PK0)* D9(PF5)* D10(PG15)* D12(PD2)* D13(PC7)* D14(PC9)* D15(PC11)* D16(JTDI)* D17(JTCK-SWCLK)* D20(DDR_DQ22)* D21(DDR_DQ17)* D22(DDR_DQ18)* E1(PI2)* E2(PI1)* E3(PI3)* E4(PE12)* E6(PH9)* E7(PK1)* E8(PK2)* E9(PE6)* E10(PF0)* E11(PA15)* E12(PC12)* E13(PC6)* E14(PC8)* E15(NJTRST)* E16(JTDO-TRACESWO)* E17(JTMS-SWDIO)* E22(DDR_DQ21)* F1(PI7)* F2(PI5)* F3(PI15)* F4(PZ3)* F5(PH12)* F9(PF4)* F10(PD7)* F11(PB7)* F12(PB9)* F13(PF2)* F14(PC10)* F15(PE4)* G1(PZ4)* G2(PZ0)* G3(PZ6)* G5(PI6)* H1(PI13)* H2(PI12)* H3(PZ7)* H4(PZ5)* H5(PZ1)* H6(PJ8)* J1(PJ3)* J2(PJ0)* J3(PJ10)* J4(PG12)* J5(PI9)* J6(PI4)* K1(PJ5)* K2(PJ4)* K4(PJ2)* K5(PZ2)* K6(PJ11)* K21(DDR_DTO1)* L1(PD15)* L2(PJ9)* L3(PD6)* L4(PJ7)* L5(PJ6)* L6(PJ1)* L22(DDR_DTO0)* M1(PD8)* M2(PD9)* M3(PD14)* N1(PI8)* N2(PC13)* N3(BOOT0)* N4(BOOT1)* P1(PC14-OSC32_IN)* P2(PC15-OSC32_OUT)* P4(BOOT2)* R1(NRST_CORE)* R3(PA14)* R4(ANA0)* T1(PH0-OSC_IN)* T2(PH1-OSC_OUT)* T3(PI11)* T4(PA3)* T5(ANA1)* U1(PWR_LP)* U2(PDR_ON_CORE)* U3(PC3)* U4(PG3)* U5(PA5)* U8(PG5)* U10(PC0)* U11(PG11)* V2(PDR_ON)* V3(PF3)* V4(PA1)* V6(PA4)* V7(PF14)* V8(PF12)* V9(PB10)* V10(PB13)* V11(PH6)* V12(PF10)* V13(PB2)* V15(USBO_VBUS)* V22(DDR_DQ24)* W1(PI10)* W2(PH7)* W3(PA13)* W4(PG2)* W5(PG0)* W6(PF15)* W7(PF13)* W8(PF11)* W9(PA6)* W10(PE7)* W11(PE9)* W13(PB6)* W14(PE10)* W15(PG9)* W16(PA12)* W20(DDR_DQ25)* W21(DDR_DQ31)* W22(DDR_DQ30)* Y1(PC2)* Y2(PE2)* Y4(PG1)* Y5(PB11)* Y6(PH3)* Y8(PG8)* Y9(PA7)* Y11(PG7)* Y12(PE8)* Y16(PA11)* Y17(PA10)* Y21(DDR_DQS3P)* Y22(DDR_DQS3N)*

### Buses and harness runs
bus SDMMC2_D[0..7] = port SDMMC2_D[0..7]

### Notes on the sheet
- eMMC
- POWER - PMIC

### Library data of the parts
C50 = MCD-00006: as C36 on sheet Power_MPU
R27 = MCD-00120: Resistor,240R,0402,1%,1/16W; Manufacturer_Part_Number: RC0402FR-07240RL; Manufacturer: YAGEO; Provided_By: SUBCO; ECCN_US: EAR99; ECCN_EU: NEC
R37 R38 = MCD-00068: Resistor,1K5,0402,1%,1/16W; Manufacturer_Part_Number: RC0402FR-071K5L; Manufacturer: YAGEO; Provided_By: SUBCO; ECCN_US: EAR99; ECCN_EU: NEC
U1 = MCD-00618: as U1 on sheet Power_MPU

## Sheet 1DDR3L_16bits.SchDoc: 1DDR3L_16bits
size A3; Date: Not used; ApprovedBy: Not used; CheckedBy: Not used; Author: Not used; CompanyName: STMicroelectronics; DrawnBy: Not used; Engineer: Not used; Organization: Not used; Address1: Not used; Address2: Not used; Address3: Not used; Address4: Not used; DocumentNumber: Not used; Revision: Not used; SheetNumber: 7; SheetTotal: 7
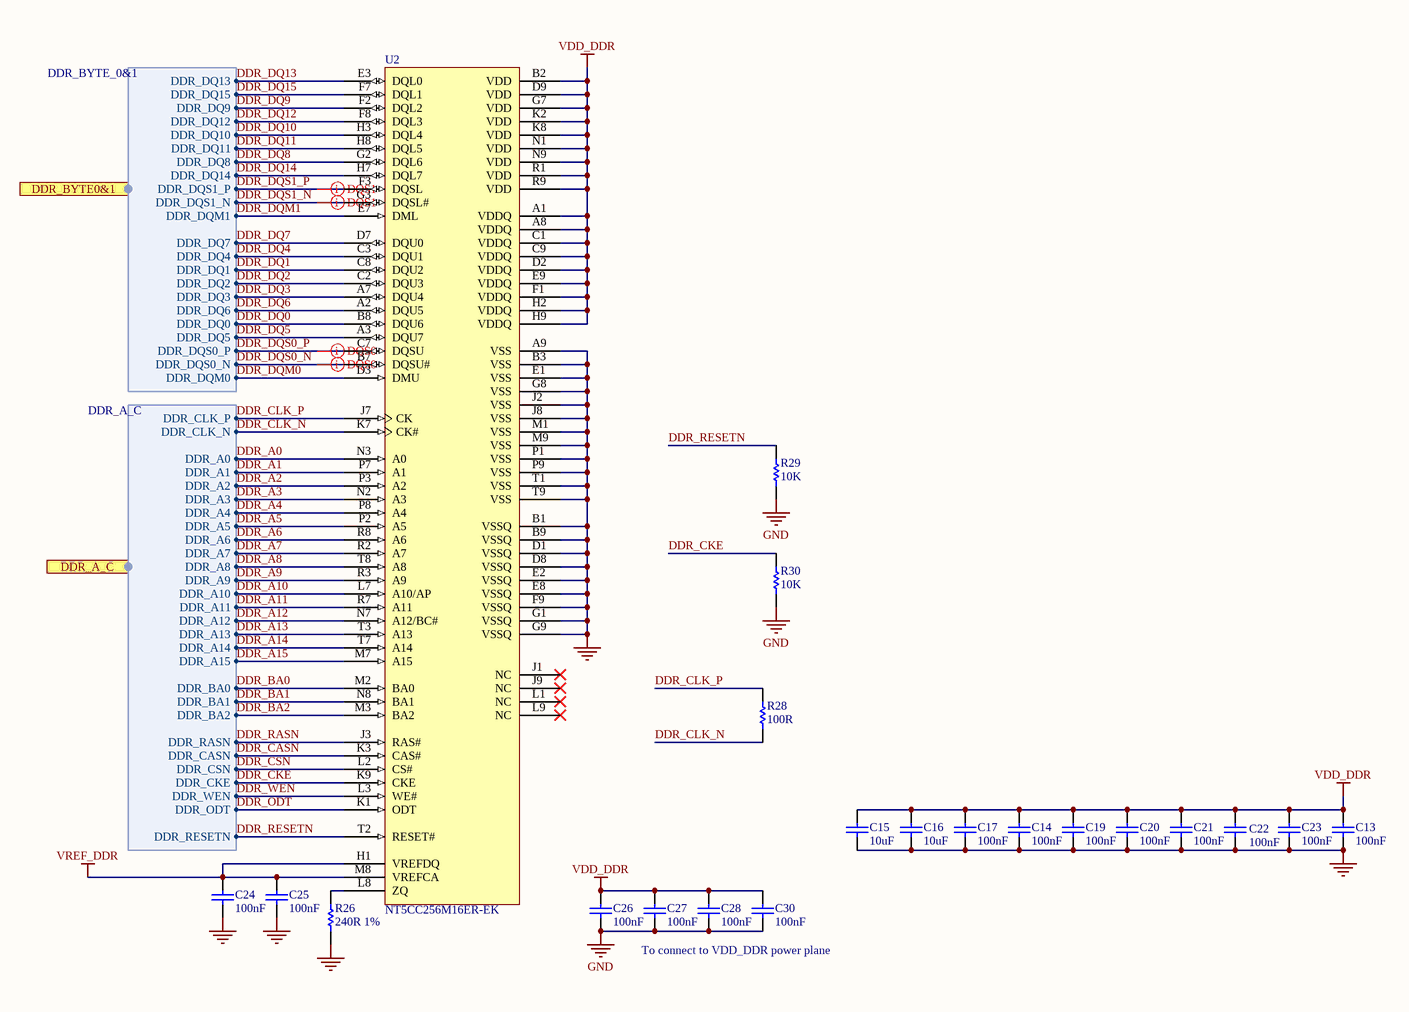
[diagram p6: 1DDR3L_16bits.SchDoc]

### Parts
C13  value 100nF  [C0402]  (hidden comment: Capacitor)
C14  value 100nF  [C0402]  (hidden comment: Capacitor)
C15  value 10uF  [C0603]  (hidden comment: Capacitor)
C16  value 10uF  [C0603]  (hidden comment: Capacitor)
C17  value 100nF  [C0402]  (hidden comment: Capacitor)
C19  value 100nF  [C0402]  (hidden comment: Capacitor)
C20  value 100nF  [C0402]  (hidden comment: Capacitor)
C21  value 100nF  [C0402]  (hidden comment: Capacitor)
C22  value 100nF  [C0402]  (hidden comment: Capacitor)
C23  value 100nF  [C0402]  (hidden comment: Capacitor)
C24  value 100nF  [C0402]  (hidden comment: Capacitor)
C25  value 100nF  [C0402]  (hidden comment: Capacitor)
C26  value 100nF  [C0402]  (hidden comment: Capacitor)
C27  value 100nF  [C0402]  (hidden comment: Capacitor)
C28  value 100nF  [C0402]  (hidden comment: Capacitor)
C30  value 100nF  [C0402]  (hidden comment: Capacitor)
R26  value 240R 1%  [R0402]  (hidden comment: Resistor)
R28  value 100R  [R0402]  (hidden comment: Resistor)
R29  value 10K  [R0402]  (hidden comment: Resistor)
R30  value 10K  [R0402]  (hidden comment: Resistor)
U2  NT5CC256M16ER-EK  [ICC_VFBGA96_9x13_P080]

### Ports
DDR_A_C (harness DDR_A_C), DDR_BYTE0&1 (harness DDR_BYTE_0&1)

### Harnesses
DDR_BYTE_0&1: DDR_DQ10, DDR_DQ13, DDR_DQ9, DDR_DQ15, DDR_DQ8, DDR_DQ12, DDR_DQ11, DDR_DQ14, DDR_DQS1_P, DDR_DQS1_N, DDR_DQ1, DDR_DQM1, DDR_DQ7, DDR_DQ3, DDR_DQ4, DDR_DQ2, DDR_DQ6, DDR_DQ0, DDR_DQ5, DDR_DQS0_P, DDR_DQS0_N, DDR_DQM0
DDR_A_C: DDR_A4, DDR_A0, DDR_A2, DDR_A1, DDR_A6, DDR_A3, DDR_A5, DDR_A7, DDR_A8, DDR_A9, DDR_A14, DDR_A10, DDR_A12, DDR_A11, DDR_BA0, DDR_A13, DDR_A15, DDR_BA1, DDR_BA2, DDR_RASN, DDR_CASN, DDR_CSN, DDR_CKE, DDR_WEN, DDR_ODT, DDR_CLK_P, DDR_CLK_N, DDR_RESETN

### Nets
GND: C13.1 C14.1 C15.1 C16.1 C17.1 C19.1 C20.1 C21.1 C22.2 C23.1 C24.1 C25.1 C26.1 C27.1 C28.1 C30.1 R26.1 R29.1 R30.1 U2.A9(VSS) U2.B1(VSSQ) U2.B3(VSS) U2.B9(VSSQ) U2.D1(VSSQ) U2.D8(VSSQ) U2.E1(VSS) U2.E2(VSSQ) U2.E8(VSSQ) U2.F9(VSSQ) U2.G1(VSSQ) U2.G8(VSS) U2.G9(VSSQ) U2.J2(VSS) U2.J8(VSS) U2.M1(VSS) U2.M9(VSS) U2.P1(VSS) U2.P9(VSS) U2.T1(VSS) U2.T9(VSS)
VDD_DDR: C13.2 C14.2 C15.2 C16.2 C17.2 C19.2 C20.2 C21.2 C22.1 C23.2 C26.2 C27.2 C28.2 C30.2 U2.A1(VDDQ) U2.A8(VDDQ) U2.B2(VDD) U2.C1(VDDQ) U2.C9(VDDQ) U2.D2(VDDQ) U2.D9(VDD) U2.E9(VDDQ) U2.F1(VDDQ) U2.G7(VDD) U2.H2(VDDQ) U2.H9(VDDQ) U2.K2(VDD) U2.K8(VDD) U2.N1(VDD) U2.N9(VDD) U2.R1(VDD) U2.R9(VDD)
VREF_DDR: C24.2 C25.2 U2.H1(VREFDQ) U2.M8(VREFCA)
DDR_A0: U2.N3(A0) ; port DDR_A_C.DDR_A0
DDR_A1: U2.P7(A1) ; port DDR_A_C.DDR_A1
DDR_A2: U2.P3(A2) ; port DDR_A_C.DDR_A2
DDR_A3: U2.N2(A3) ; port DDR_A_C.DDR_A3
DDR_A4: U2.P8(A4) ; port DDR_A_C.DDR_A4
DDR_A5: U2.P2(A5) ; port DDR_A_C.DDR_A5
DDR_A6: U2.R8(A6) ; port DDR_A_C.DDR_A6
DDR_A7: U2.R2(A7) ; port DDR_A_C.DDR_A7
DDR_A8: U2.T8(A8) ; port DDR_A_C.DDR_A8
DDR_A9: U2.R3(A9) ; port DDR_A_C.DDR_A9
DDR_A10: U2.L7(A10/AP) ; port DDR_A_C.DDR_A10
DDR_A11: U2.R7(A11) ; port DDR_A_C.DDR_A11
DDR_A12: U2.N7(A12/BC#) ; port DDR_A_C.DDR_A12
DDR_A13: U2.T3(A13) ; port DDR_A_C.DDR_A13
DDR_A14: U2.T7(A14) ; port DDR_A_C.DDR_A14
DDR_A15: U2.M7(A15) ; port DDR_A_C.DDR_A15
DDR_BA0: U2.M2(BA0) ; port DDR_A_C.DDR_BA0
DDR_BA1: U2.N8(BA1) ; port DDR_A_C.DDR_BA1
DDR_BA2: U2.M3(BA2) ; port DDR_A_C.DDR_BA2
DDR_CASN: U2.K3(CAS#) ; port DDR_A_C.DDR_CASN
DDR_CKE: R30.2 U2.K9(CKE) ; port DDR_A_C.DDR_CKE
DDR_CLK_N: R28.1 U2.K7(CK#) ; port DDR_A_C.DDR_CLK_N
DDR_CLK_P: R28.2 U2.J7(CK) ; port DDR_A_C.DDR_CLK_P
DDR_CSN: U2.L2(CS#) ; port DDR_A_C.DDR_CSN
DDR_DQ0: U2.B8(DQU6) ; port DDR_BYTE0&1.DDR_DQ0
DDR_DQ1: U2.C8(DQU2) ; port DDR_BYTE0&1.DDR_DQ1
DDR_DQ2: U2.C2(DQU3) ; port DDR_BYTE0&1.DDR_DQ2
DDR_DQ3: U2.A7(DQU4) ; port DDR_BYTE0&1.DDR_DQ3
DDR_DQ4: U2.C3(DQU1) ; port DDR_BYTE0&1.DDR_DQ4
DDR_DQ5: U2.A3(DQU7) ; port DDR_BYTE0&1.DDR_DQ5
DDR_DQ6: U2.A2(DQU5) ; port DDR_BYTE0&1.DDR_DQ6
DDR_DQ7: U2.D7(DQU0) ; port DDR_BYTE0&1.DDR_DQ7
DDR_DQ8: U2.G2(DQL6) ; port DDR_BYTE0&1.DDR_DQ8
DDR_DQ9: U2.F2(DQL2) ; port DDR_BYTE0&1.DDR_DQ9
DDR_DQ10: U2.H3(DQL4) ; port DDR_BYTE0&1.DDR_DQ10
DDR_DQ11: U2.H8(DQL5) ; port DDR_BYTE0&1.DDR_DQ11
DDR_DQ12: U2.F8(DQL3) ; port DDR_BYTE0&1.DDR_DQ12
DDR_DQ13: U2.E3(DQL0) ; port DDR_BYTE0&1.DDR_DQ13
DDR_DQ14: U2.H7(DQL7) ; port DDR_BYTE0&1.DDR_DQ14
DDR_DQ15: U2.F7(DQL1) ; port DDR_BYTE0&1.DDR_DQ15
DDR_DQM0: U2.D3(DMU) ; port DDR_BYTE0&1.DDR_DQM0
DDR_DQM1: U2.E7(DML) ; port DDR_BYTE0&1.DDR_DQM1
DDR_DQS0_N: U2.B7(DQSU#) ; port DDR_BYTE0&1.DDR_DQS0_N
DDR_DQS0_P: U2.C7(DQSU) ; port DDR_BYTE0&1.DDR_DQS0_P
DDR_DQS1_N: U2.G3(DQSL#) ; port DDR_BYTE0&1.DDR_DQS1_N
DDR_DQS1_P: U2.F3(DQSL) ; port DDR_BYTE0&1.DDR_DQS1_P
DDR_ODT: U2.K1(ODT) ; port DDR_A_C.DDR_ODT
DDR_RASN: U2.J3(RAS#) ; port DDR_A_C.DDR_RASN
DDR_RESETN: R29.2 U2.T2(RESET#) ; port DDR_A_C.DDR_RESETN
DDR_WEN: U2.L3(WE#) ; port DDR_A_C.DDR_WEN
NetR26_2: R26.2 U2.L8(ZQ)

Not connected (* = marked no-connect by the designer): U2 J1(NC)* J9(NC)* L1(NC)* L9(NC)*

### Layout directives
differential pair: DDR_DQS0_N, DDR_DQS0_P, DDR_DQS1_N, DDR_DQS1_P

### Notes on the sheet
- To connect to VDD_DDR power plane

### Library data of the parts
C13 C14 C17 C19-C28 C30 = MCD-00006: as C36 on sheet Power_MPU
C15 C16 = MCD-00099: as C18 on sheet Power_PMIC
R26 = MCD-00120: as R27 on sheet STM32_MPU_IOs
R28 = MCD-00067: Resistor,100R,0402,1%,1/16W; Manufacturer_Part_Number: RC0402FR-07100RL; Manufacturer: YAGEO; ECCN_US: EAR99; ECCN_EU: NEC; Provided_By: SUBCO
R29 R30 = MCD-00053: as R40 on sheet eMMC
U2 = MCD-01811: Memory,DDR3L,4Gb,256Mbx16,933Mhz,1V35,TFBGA; Part_Type: IC; Manufacturer: NANYA; BMS_Part_Number: 9171435; ECCN_US: tbd; Provided_By: SUBCO

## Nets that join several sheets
3V3: Power_PMIC (5 pins), eMMC (6 pins)
GND: Power_PMIC (28 pins), Power_MPU (140 pins), eMMC (17 pins), STM32_MPU_IOs (C50.1 R27.2 U1.AA12), 1DDR3L_16bits (40 pins)
VDD: Power_PMIC (C38.2 L3.2 U4.31 U4.42), Power_MPU (23 pins), eMMC (8 pins), STM32_MPU_IOs (R37.1 R38.1)
VDD_CORE: Power_PMIC (C34.2 L1.2 U4.5), Power_MPU (40 pins)
VDD_DDR: Power_PMIC (5 pins), Power_MPU (24 pins), 1DDR3L_16bits (32 pins)
VDD_USB: Power_PMIC (C52.2 U4.39), Power_MPU (C36.2 U1.AB13 U1.AB16)
VDDA: Power_PMIC (C49.2 U4.20), Power_MPU (C76.2 R96.1 U1.R5)
VREF_DDR: Power_PMIC (C45.2 U4.16), STM32_MPU_IOs (C50.2 U1.AB19), 1DDR3L_16bits (C24.2 C25.2 U2.H1 U2.M8)
DDR_A0: STM32_MPU_IOs (U1.K19), 1DDR3L_16bits (U2.N3)
DDR_A1: STM32_MPU_IOs (U1.M18), 1DDR3L_16bits (U2.P7)
DDR_A2: STM32_MPU_IOs (U1.J18), 1DDR3L_16bits (U2.P3)
DDR_A3: STM32_MPU_IOs (U1.J19), 1DDR3L_16bits (U2.N2)
DDR_A4: STM32_MPU_IOs (U1.T18), 1DDR3L_16bits (U2.P8)
DDR_A5: STM32_MPU_IOs (U1.H19), 1DDR3L_16bits (U2.P2)
DDR_A6: STM32_MPU_IOs (U1.U19), 1DDR3L_16bits (U2.R8)
DDR_A7: STM32_MPU_IOs (U1.F18), 1DDR3L_16bits (U2.R2)
DDR_A8: STM32_MPU_IOs (U1.U18), 1DDR3L_16bits (U2.T8)
DDR_A9: STM32_MPU_IOs (U1.H18), 1DDR3L_16bits (U2.R3)
DDR_A10: STM32_MPU_IOs (U1.N18), 1DDR3L_16bits (U2.L7)
DDR_A11: STM32_MPU_IOs (U1.P19), 1DDR3L_16bits (U2.R7)
DDR_A12: STM32_MPU_IOs (U1.N19), 1DDR3L_16bits (U2.N7)
DDR_A13: STM32_MPU_IOs (U1.G18), 1DDR3L_16bits (U2.T3)
DDR_A14: STM32_MPU_IOs (U1.P18), 1DDR3L_16bits (U2.T7)
DDR_A15: STM32_MPU_IOs (U1.M19), 1DDR3L_16bits (U2.M7)
DDR_BA0: STM32_MPU_IOs (U1.K20), 1DDR3L_16bits (U2.M2)
DDR_BA1: STM32_MPU_IOs (U1.R18), 1DDR3L_16bits (U2.N8)
DDR_BA2: STM32_MPU_IOs (U1.K18), 1DDR3L_16bits (U2.M3)
DDR_CASN: STM32_MPU_IOs (U1.M22), 1DDR3L_16bits (U2.K3)
DDR_CKE: STM32_MPU_IOs (U1.R19), 1DDR3L_16bits (R30.2 U2.K9)
DDR_CLK_N: STM32_MPU_IOs (U1.N21), 1DDR3L_16bits (R28.1 U2.K7)
DDR_CLK_P: STM32_MPU_IOs (U1.N20), 1DDR3L_16bits (R28.2 U2.J7)
DDR_CSN: STM32_MPU_IOs (U1.L18), 1DDR3L_16bits (U2.L2)
DDR_DQ0: STM32_MPU_IOs (U1.E21), 1DDR3L_16bits (U2.B8)
DDR_DQ1: STM32_MPU_IOs (U1.F21), 1DDR3L_16bits (U2.C8)
DDR_DQ2: STM32_MPU_IOs (U1.H21), 1DDR3L_16bits (U2.C2)
DDR_DQ3: STM32_MPU_IOs (U1.E20), 1DDR3L_16bits (U2.A7)
DDR_DQ4: STM32_MPU_IOs (U1.J21), 1DDR3L_16bits (U2.C3)
DDR_DQ5: STM32_MPU_IOs (U1.H20), 1DDR3L_16bits (U2.A3)
DDR_DQ6: STM32_MPU_IOs (U1.H22), 1DDR3L_16bits (U2.A2)
DDR_DQ7: STM32_MPU_IOs (U1.G19), 1DDR3L_16bits (U2.D7)
DDR_DQ8: STM32_MPU_IOs (U1.N22), 1DDR3L_16bits (U2.G2)
DDR_DQ9: STM32_MPU_IOs (U1.R21), 1DDR3L_16bits (U2.F2)
DDR_DQ10: STM32_MPU_IOs (U1.P21), 1DDR3L_16bits (U2.H3)
DDR_DQ11: STM32_MPU_IOs (U1.T20), 1DDR3L_16bits (U2.H8)
DDR_DQ12: STM32_MPU_IOs (U1.V20), 1DDR3L_16bits (U2.F8)
DDR_DQ13: STM32_MPU_IOs (U1.R20), 1DDR3L_16bits (U2.E3)
DDR_DQ14: STM32_MPU_IOs (U1.U21), 1DDR3L_16bits (U2.H7)
DDR_DQ15: STM32_MPU_IOs (U1.V21), 1DDR3L_16bits (U2.F7)
DDR_DQM0: STM32_MPU_IOs (U1.G20), 1DDR3L_16bits (U2.D3)
DDR_DQM1: STM32_MPU_IOs (U1.T21), 1DDR3L_16bits (U2.E7)
DDR_DQS0_N: STM32_MPU_IOs (U1.G21), 1DDR3L_16bits (U2.B7)
DDR_DQS0_P: STM32_MPU_IOs (U1.G22), 1DDR3L_16bits (U2.C7)
DDR_DQS1_N: STM32_MPU_IOs (U1.R22), 1DDR3L_16bits (U2.G3)
DDR_DQS1_P: STM32_MPU_IOs (U1.T22), 1DDR3L_16bits (U2.F3)
DDR_ODT: STM32_MPU_IOs (U1.L21), 1DDR3L_16bits (U2.K1)
DDR_RASN: STM32_MPU_IOs (U1.M20), 1DDR3L_16bits (U2.J3)
DDR_RESETN: STM32_MPU_IOs (U1.F19), 1DDR3L_16bits (R29.2 U2.T2)
DDR_WEN: STM32_MPU_IOs (U1.M21), 1DDR3L_16bits (U2.L3)
I2C4_SCL: Power_PMIC (U4.4), STM32_MPU_IOs (R37.2 U1.W12)
I2C4_SDA: Power_PMIC (U4.3), STM32_MPU_IOs (R38.2 U1.V14)
NRST: Power_PMIC (U4.1), STM32_MPU_IOs (U1.R2)
PA0_WKUP: Power_PMIC (U4.43), STM32_MPU_IOs (U1.AA3)
PWR_ON: Power_PMIC (U4.44), STM32_MPU_IOs (U1.V1)

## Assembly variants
Example: not fitted R34 R42 R42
